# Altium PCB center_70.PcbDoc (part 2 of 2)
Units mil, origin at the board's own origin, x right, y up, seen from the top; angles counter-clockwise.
Board outline 2598.41 x 2598.41 mil, 6 copper layers (Top Layer 1, GND, POWER, SIG, GND (Mid4), Bottom Layer 1), stack 67.411 mil thick; 185 components, 89 nets, 515 pads, 179 vias.
Unrouted connection lines stored in the file: 158.
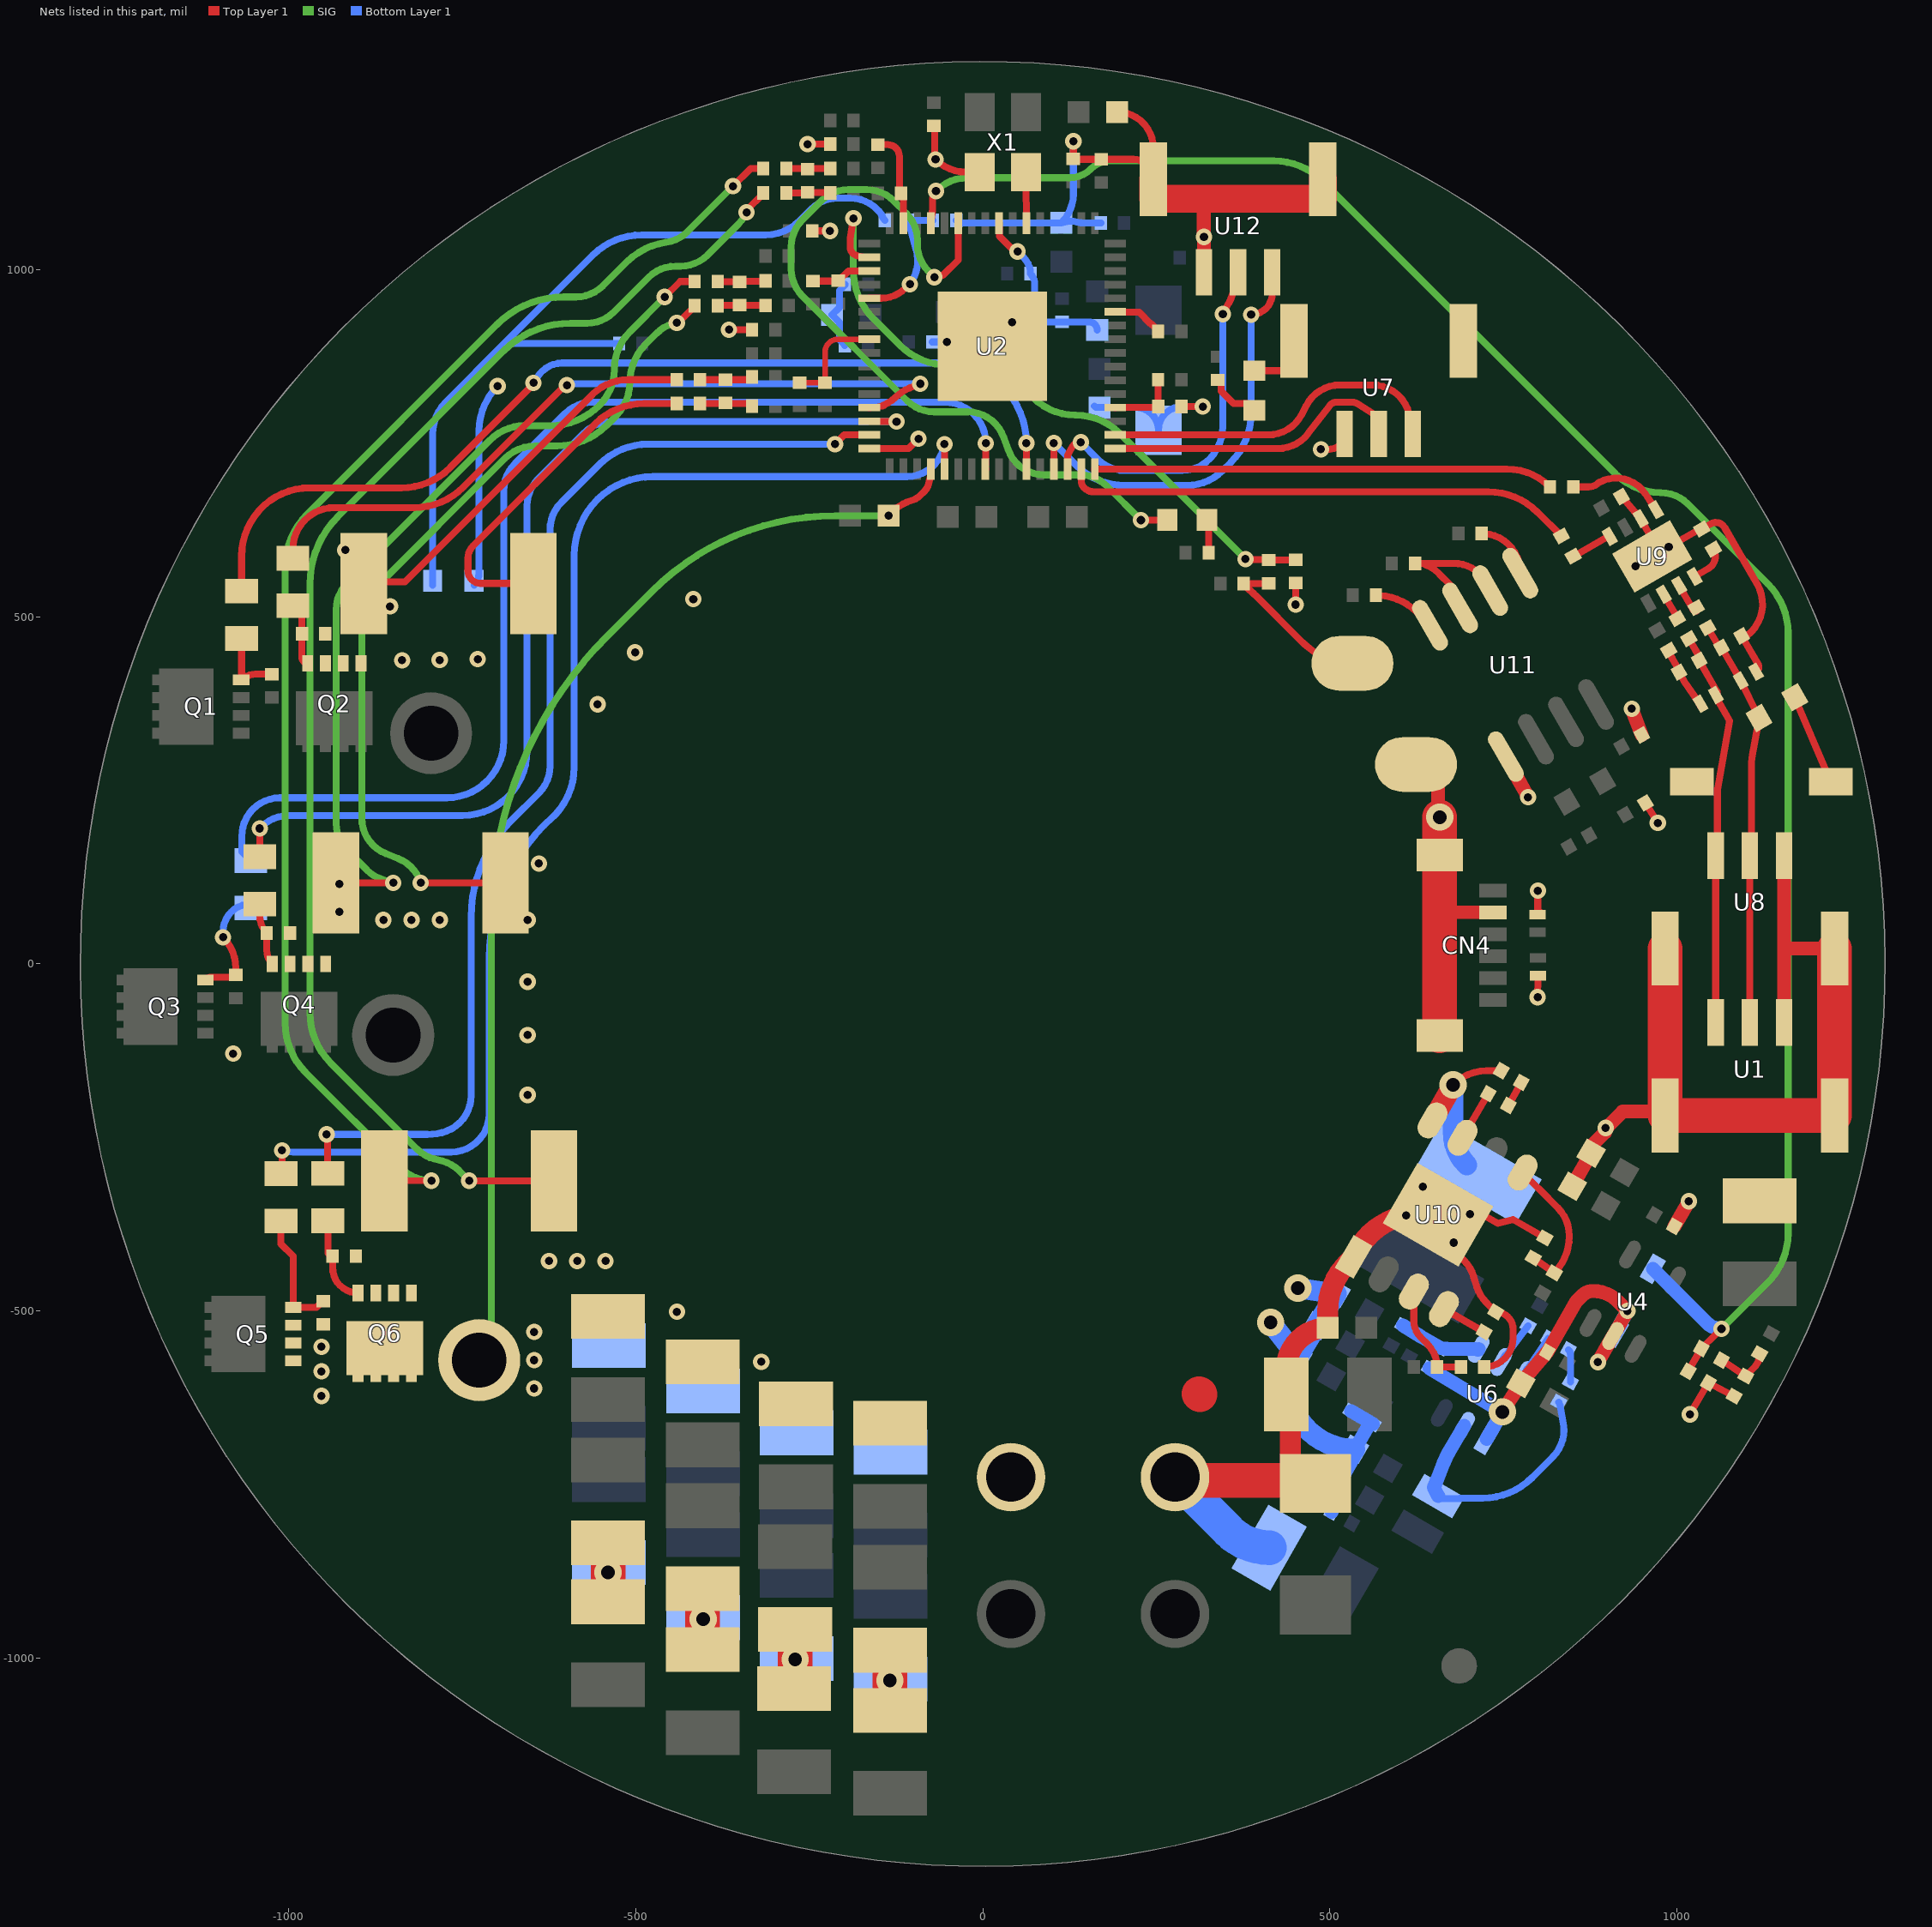
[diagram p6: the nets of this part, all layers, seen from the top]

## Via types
v1: diameter 23.62, hole 11.81, Top Layer 1 to Bottom Layer 1, 146 vias
v2: diameter 39.37, hole 19.68, Top Layer 1 to Bottom Layer 1, 21 vias
v3: diameter 86.61, hole 86.61, Top Layer 1 to Bottom Layer 1, 6 vias
v4: diameter 19.68, hole 11.81, Top Layer 1 to Bottom Layer 1, 4 vias
v5: diameter 19.68, hole 11.81, Top Layer 1 to Bottom Layer 1, tented top, 2 vias

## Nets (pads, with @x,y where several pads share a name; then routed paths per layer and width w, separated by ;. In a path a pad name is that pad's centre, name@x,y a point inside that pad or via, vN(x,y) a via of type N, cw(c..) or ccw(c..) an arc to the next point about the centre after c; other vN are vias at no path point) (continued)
C: C36.1 C.1 Q5.S Q6.D R11.2 U2.36 | length 1650.3
  Top Layer 1 w10: v1(-135.38,645.28) -124.63,656.02 -120.42,658.91 cw(c-89.35,613.52) -108.64,665.03 -97.72,669.12 ccw(c-103.69,685.04) -91.69,673 -82.96,681.72 ccw(c-95,693.72) -78.55,689.46 -77.36,694.03 -75.31,702.04 U2.36@-74.8,712.59
  SIG w10: C.1@-725,-570.47 -723.35,-568.82 ccw(c-762.28,-529.97) -707.28,-529.97 -707.28,68.96 -707.07,84.62 cw(c-136.94,69.06) -540.42,472.17 -476.62,535.97 cw(c-212.74,272.09) -212.74,645.28 v1(-135.38,645.28)
  other v1: -645.87,-611.22 -952.17,-586.61 -645.87,-570.47 -645.87,-529.92
CAN_RX: R30.1 U2.47 | length 739.1
  Top Layer 1 w10: U2.47@141.73,712.59 141.73,695.89 ccw(c156.52,695.89) 146.06,685.43 ccw(c159.85,699.22) 159.85,679.72 728.02,679.72 cw(c728.02,579.72) 798.73,650.44 R30.1@833.19,615.97
CAN_TX: R27.1 U2.48 | length 662.2
  Top Layer 1 w10: U2.48@161.42,712.59 754.5,712.59 cw(c754.5,624.58) R27.1@816.73,686.81
CANH: C30.1 Q7.2 R28.2 R56.1 U1.2 U8.2 | length 571.5
  Top Layer 1 w10: R28.2@1044.05,484.01 1059.8,456.73 ccw(c1062.35,458.21) C30.1@1063.83,455.65 Q7.2@1091.39,407.92 1094.38,401.78 1112.99,363.69 R56.1@1117.71,354.01 1115.28,340.67 1107.97,300.63 ccw(c1162.08,290.76) 1107.08,290.76 1107.08,175.07 U8.2@1107.08,146.6 ; U1.2@1104.52,-84.38 U8.2@1104.52,127.51
CANL: C31.2 Q8.2 R29.2 U1.1 U8.1 U13.1 | length 548.1
  Top Layer 1 w10: R29.2@1016.77,468.26 1032.52,440.98 cw(c1029.96,439.51) C31.2@1031.44,436.95 1057.03,392.62 cw(c1053.62,390.66) Q8.2@1055.59,387.25 ; U1.1@1055.31,-84.38 U8.1@1055.31,155.97 ; Q8.2@1056.57,382.72 1075.39,350.13 1057.87,251.64 U8.1@1057.87,175.07
GND: C3.1 C4.1 C5.1 C6.1 C7.1 C8.1 C9.1 C10.1 C11.1 C12.1 C13.1 C14.1 C15.1 C16.1 C17.1 C19.1 C20.1 C25.1 C28.1 C29.1 C30.2 C31.1 C34.1 C35.1 C38.1 C39.1 C40.1 C42.1 C43.1 C44.1 C45.1 C46.1 C47.1 C48.1 C49.1 C50.1 C51.1 C52.1 C53.1 C54.1 C55.1 C56.1 C57.1 C58.1 C59.1 C60.1 C61.1 C62.1 C63.1 C67.1 C68.1 C70.1 C71.1 C72.1 C73.1 C74.1 C78.1 C79.1 C85.1 C86.1 C87.1 CN1.1 CN2.1 CN4.2 CN4.7 CN4.8 D1.2 NTC2.1 Q7.1 Q8.1 Q9.A Q10.1 Q11.K Q13.A Q14.1 R2.1 R3.1 R5.1 R23.1 R24.1 R25.1 R26.2 R34.1 R36.1 R38.2 R43.1 R50.1 R55.1 R58.1 R59.1 R60.1 R66.2 R79.1 U1.3 U1.4 U1.5 U2.32 U2.65 U4.2 U6.1 U7.3 U7.4 U7.5 U8.3 U8.4 U8.5 U9.2 U9.9 U10.1 U10.9 U11.5 U12.3 U12.4 U12.5 X1.2 | length 11395.8
  Top Layer 1 w10: v1(-809.25,116.73) R55.1@-687.2,116.73 ; v1(-739.38,-312.17) R5.1@-617.33,-312.17 ; R3.1@-647.05,547.83 -723.03,547.83 cw(c-723.03,565.94) -741.14,565.94 -741.14,584.45 cw(c-716.8,584.45) -734.01,601.66 -558.29,777.39 cw(c-487.58,706.68) -487.58,806.68 R34.1@-440.55,806.68 ; v1(-440.55,923.02) -438.67,923.02 -414.96,946.74 R59.1@-414.96,947.72 ; v1(-365.44,913.18) R58.1@-332.09,913.18 ; v1(-339.96,1082.08) -339.96,1085.04 -316.15,1108.85 R36.1@-316.15,1109.84 ; v1(-252.17,1180.21) R60.1@-219.5,1180.21 ; R43.1@-245.28,1055.37 v1@-219.89,1055.36 ; U2.32@-163.19,741.92 -106.7,741.92 v1(-92.52,756.09) ; C48.1@-70.28,1206.69 -69.09,1205.51 -69.09,1159.45 v1(-67.91,1158.27) ccw(c-23.72,1202.47) -23.72,1139.96 X1.2@-4.53,1139.96 ; v1(130.51,1184.45) C50.1@130.51,1159.25 ccw(c131.3,1159.25) 131.3,1158.47 C19.1@170.67,1158.47 216.86,1158.47 cw(c216.86,1129.73) U12.4@245.59,1129.73 245.59,1174.62 ccw(c193.64,1174.62) C44.1@193.64,1226.57 ; R38.2@286.22,802.36 v1(316.73,802.36) ; Q11.K@391.14,854.14 448.03,854.14 U7.4@448.03,897.05 ; C86.1@449.61,548.43 C86.1@450.59,548.43 v1(450.59,517.32) ; v1(487.01,740.94) 498.62,740.94 ccw(c498.62,763.19) U7.3@520.86,763.19 ; U10.9@655.75,-361.12 664.51,-369.88 cw(c625.62,-408.77) 680.09,-401.18 680.1,-401.26 687.48,-422.15 687.69,-422.27 cw(c680.19,-435.27) 690.78,-424.64 692.88,-426.74 cw(c653.94,-465.59) 706.37,-448.96 711.52,-465.19 ccw(c763.94,-448.56) 725.05,-487.45 727.38,-489.78 ccw(c766.37,-450.99) 727.57,-489.97 734.07,-496.47 735.27,-497.17 R23.1@738.63,-501.03 cw(c738.63,-526.11) 763.71,-526.11 763.71,-538.54 cw(c721.94,-538.54) R2.1@721.94,-580.31 ; v4(701.65,-360.35) 713.26,-357.24 741.7,-373.66 763.71,-367.76 R24.1@809.43,-394.16 ; v1(799.02,-47.88) 799.36,-20.72 799.36,-18.82 Q10.1@799.41,-16.93 ; Q14.1@799.02,71.06 804.05,72.95 Q14.1@802.48,74.53 ; v1(799.36,105.51) 799.19,105.34 799.19,72.95 Q14.1@802.48,72.95 ; C20.1@919.65,673.03 922.87,669.3 942.28,646.8 U9.2@947.14,641.17 967.57,605.79 ccw(c980.35,613.17) v5(987.73,600.39) 1033.33,626.72 cw(c1034.07,625.44) R26.2@1035.34,626.18 1048.13,633.56 cw(c1055.51,620.77) 1068.3,628.16 1115.05,547.18 cw(c1064.76,518.14) C30.2@1093.79,467.85 ; R66.2@954.06,231.79 956.62,227.68 v1(972.05,202.95) ; C49.1@987.79,451.53 988.44,447.45 992.36,440.66 cw(c944.77,413.09) 992.54,440.35 992.83,439.85 cw(c945.24,412.27) 992.92,439.68 1001.31,425.15 C31.1@1002.46,420.22 1004.88,416.02 1010.79,405.78 ccw(c1058.33,433.44) 1013.36,401.78 1026.71,382.81 cw(c981.74,351.15) 1028.18,380.61 1028.76,379.62 Q8.1@1034.41,369.92 ; v1(1018.24,-648.55) 1042.36,-607.43 C29.1@1044.81,-603.25 1048.35,-604.83 1051.88,-606.87 1077.57,-620.03 R50.1@1081.89,-622.24 ; C30.2@1092.81,472.38 1116.43,431.47 cw(c1109.61,427.53) Q7.1@1113.55,420.71
  Top Layer 1 w20: 318.31,1101.69 318.31,1046.65 v1(318.5,1046.65) 318.5,995.87 U12.3@318.43,995.87 ; NTC2.1@655.51,271.71 655.51,213.94 v2(658.07,211.38) ; 658.07,74.53 CN4.2@734.84,74.01 ; v2(748.03,-644.88) 769.28,-612.19 ccw(c677.06,-552.23) 771.58,-608.5 C13.1@774.79,-603.72 778.9,-599.45 778.94,-599.38 cw(c868.45,-663.33) 784.37,-592.4 C14.1@812.87,-558.71 854.45,-486.34 863.72,-477.06 cw(c878.55,-491.88) 878.55,-470.92 cw(c878.55,-521.82) 914.54,-485.83 v1(928.35,-499.63) 913.48,-525.37 U4.2@907.58,-535.6 901.67,-545.83 v1(885.83,-573.28) ; U11.5@753.21,298.49 765.16,277.78 764.67,277.5 v1(785.16,239.99) ; C15.1@848.78,-320.32 851.61,-315.32 873.11,-277.41 C16.1@875.94,-272.41 875.94,-262.52 896.26,-242.21 896.26,-236.41 v1@895.97,-236.12 ; v1(896.95,-236.12) 897.93,-236.12 921.48,-212.57 U1.5@970.46,-212.57 ; v1(934.45,367.54) C85.1@948.94,329.63 ; C17.1@995.94,-378.01 v1(1016.55,-341.79) ; U1.3@1153.74,-84.38 1153.74,22.11 ; U8.3@1153.74,155.97 1153.74,22.11 ; U8.4@1226.57,22.11 1153.74,22.11
  Top Layer 1 w30: Q13.A@479.22,-747.76 470.37,-747.76 443.04,-720.44 443.04,-625.75 C72.1@437.16,-619.87 437.16,-583.44 cw(c496.65,-583.44) C3.1@496.65,-523.96 496.65,-500.7 cw(c596.65,-500.7) 525.93,-429.99 U10.1@534.1,-421.82 ; U10.1@540.46,-410.81 cw(c627.06,-460.81) 601.18,-364.22 v4(609.84,-361.89)
  Top Layer 1 w40: U12.4@245.59,1129.73 245.6,1102.01 245.91,1101.69 318.31,1101.69 489.37,1101.69 489.37,1101.38 489.69,1101.69 U12.5@489.69,1129.73
  Top Layer 1 w50: C67.1@-539.38,-918.41 C53.1@-539.38,-833.56 ; C68.1@-403.35,-987.31 C71.1@-403.35,-899.5 ; C73.1@-271.46,-1043.41 ccw(c-271.46,-1042.03) -270.08,-1042.03 C54.1@-270.08,-958.36 ; C34.1@-133.46,-1074.71 C55.1@-133.46,-988.09 ; CN1.1@276.87,-738.91 281.29,-743.34 474.79,-743.34 Q13.A@479.22,-747.76 ; 311.67,-618.83 ccw(c312.7,-618.83) 312.7,-619.87 ; CN4.7@658.07,-103.15 658.07,74.53 CN4.8@658.07,156.69 v2(658.07,211.38) ; U8.5@982.48,22.11 982.48,-212.57 U1.5@982.48,-218.24 U1.4@1226.57,-218.24 U8.4@1226.57,22.11
  SIG w10: v1(-809.25,116.73) ccw(c-861.81,100.54) -841.49,151.65 -859.33,158.76 cw(c-839.09,209.91) -894.09,209.91 -894.09,498.83 cw(c-839.09,498.83) -878.03,537.68 -687.98,727.73 cw(c-644.56,684.31) -644.56,745.71 -612.84,745.71 ccw(c-612.84,845.71) -542.16,774.97 -527.95,789.17 ccw(c-576.2,837.42) -507.97,837.42 cw(c-430.3,837.42) -485.22,892.34 -469.75,907.81 cw(c-430.91,868.87) -440.64,923 v1(-440.55,923.02) ; v1(-739.38,-312.17) -739.47,-312.07 -753.67,-297.87 ccw(c-792.56,-336.77) -779.29,-283.39 -789.03,-280.97 cw(c-775.98,-227.54) -814.87,-266.43 -939.44,-141.86 cw(c-868.7,-71.18) -968.7,-71.18 -968.7,307.05 -968.7,547.1 cw(c-831.96,547.1) -928.76,643.69 -689.99,882.45 cw(c-593.4,785.66) -593.4,922.4 -570.07,922.4 ccw(c-570.07,977.4) -531.22,938.46 -481.22,988.46 cw(c-442.38,949.53) -442.38,1004.53 -435.18,1004.53 ccw(c-435.18,1059.53) -396.33,1020.59 -351.22,1065.7 ccw(c-390.16,1104.55) v1(-339.96,1082.08)
  Bottom Layer 1 w10: R79.1@-732.43,545.28 ccw(c-749.4,562.25) -725.39,562.25 -725.39,767.26 cw(c-633.99,767.26) v1(-698.62,831.89) ; C39.1@-198.62,890.16 -198.62,891.14 -206.23,898.75 -206.23,923.7 C38.1@-216.98,934.45 -206.23,945.2 -206.23,969.55 -198.23,977.56 C28.1@-198.23,978.54 ; C40.1@-72.83,895.47 v1(-51.53,895.47) -51.33,895.28 -31.3,895.28 C51.1@-31.1,895.08 ; C87.1@-38.19,1070.47 ccw(c-29.32,1079.34) -29.32,1066.8 C6.1@113.19,1066.8 ; v1@44.93,926.62 v1(42.32,924.02) 113.89,924.02 C7.1@114.19,924.31 152.95,924.31 cw(c152.95,912.45) C47.1@164.82,912.45 ; v1(130.51,1184.45) 130.51,1108.62 cw(c71.37,1108.62) C6.1@113.19,1066.8 ; C25.1@160.77,803.35 162.99,801.13 220.23,801.13 cw(c220.23,768.4) D1.2@252.95,768.4 cw(c286.91,768.4) 286.91,802.36 v1(316.73,802.36) ; C52.1@170.13,1066.8 146.78,1066.8 cw(c146.88,1121.8) 130.51,1069.29 123.94,1069.29 C6.1@113.19,1066.8 ; C45.1@316.93,1016.93 316.93,1045.08 cw(c318.5,1045.08) v1(318.5,1046.65)
  Bottom Layer 1 w20: C12.1@502.47,-788.88 C11.1@507.3,-756.12 ; C43.1@530.41,-644.02 C9.1@561.91,-662.33 ; C10.1@535.89,-698.68 538.58,-693.97 540.23,-691.1 C9.1@556.68,-662.37 ; R25.1@643.11,-582.09 v2(748.03,-644.88) U6.1@725.7,-683.82 ; Q9.A@911.61,-530.87 v1(928.35,-499.63)
  Bottom Layer 1 w30: v2(414.55,-516) 450.27,-562.06 ccw(c580.5,-460.75) 453.16,-565.67 453.3,-565.75 C35.1@453.73,-566.52 ; v2(453.73,-466.67) 507.62,-474.51 cw(c483.89,-637.79) 507.99,-474.56 508.1,-474.62 508.98,-474.7 508.71,-475.15 C5.1@508.67,-475.22 ; C5.1@508.66,-475.25 cw(c366.14,-392.1) 507.8,-476.71 507.22,-477.67 481.99,-518.67 ccw(c622.58,-605.03) 481.22,-519.93 C8.1@480.82,-520.57 480.44,-521.22 480.28,-521.49 455.09,-564.21 ccw(c597.3,-647.88) 454.49,-565.23 454.12,-565.87 C35.1@453.73,-566.52 ; C11.1@509.08,-744 C10.1@535.25,-698.68 ; C10.1@529.79,-698.68 C10.1@535.25,-698.68 ; C10.1@535.89,-698.68 cw(c535.89,-601.87) C10.1@535.25,-698.68 ; C35.1@453.73,-566.52 ccw(c489.08,-601.87) 439.08,-601.87 ccw(c535.89,-601.87) C10.1@535.25,-698.68
  Bottom Layer 1 w50: CN1.1@276.87,-738.91 354.19,-816.23 ccw(c412.51,-757.91) C42.1@412.51,-840.39
  other v1: -952.17,-622.05 -318.85,-572.78 -952.17,-551.18 -440.35,-500.79 -624.42,-427.79 -583.87,-427.79 -543.12,-427.79 -655.38,-188.57 -1079.33,-129.13 -655.38,-102.36 -655.38,-25.58 -655.38,63.19 -639.1,144.58 -554.61,373.84 -500.61,448.46 -416.73,525.2 -219.87,1055.34
  other v2: -133.66,-1031.5 -270.08,-1001.57 -402.76,-943.5 -539.57,-876.18
  other v4: 678.03,-401.26 633.46,-320.98
  other v5: 940,572.83
IA: C24.1 R39.2 U2.24 | length 154.9
  Top Layer 1 w8: C24.1@-263.58,836.99 R39.2@-227.17,836.99 ; R39.2@-227.17,836.79 R39.2@-227.17,836.99 ; U2.24@-163.19,899.4 -208.28,899.4 ccw(c-208.28,880.51) -227.17,880.51 R39.2@-227.17,836.99
IA_N: C21.1 R34.2 R42.1 | length 77.4
  Top Layer 1 w10: R34.2@-407.08,806.68 -371.26,806.68 ccw(c-371.26,807.66) C21.1@-370.28,807.66 -365.44,807.06 -335.94,807.06 R42.1@-332.09,802.94
IA_P: C21.2 R31.2 R45.1 | length 76.3
  Top Layer 1 w10: R31.2@-407.08,841.13 C21.2@-370.28,841.13 -341.59,841.13 ccw(c-341.59,854.56) R45.1@-332.09,845.06 ; R45.1@-333.27,845.26 R45.1@-333.07,845.06
IB: C22.1 R4.2 U2.19 | length 87.7
  Top Layer 1 w10: C22.1@-244.29,983.06 -208.28,983.06 R4.2@-208.28,983.93 -207.3,983.93 -193.4,997.83 U2.19@-163.19,997.83
IB_N: C26.1 R32.1 R59.2 | length 69.1
  Top Layer 1 w10: R59.2@-381.49,947.72 -381.14,948.07 -350.15,948.07 C26.1@-349.8,948.43 -349.55,948.17 -313.16,948.17 R32.1@-312.91,947.92
IB_P: C26.2 R35.1 R46.2 | length 69.4
  Top Layer 1 w10: R46.2@-381.49,982.48 -381.2,982.19 -350.1,982.19 C26.2@-349.8,981.89 -349.08,982.61 -313.62,982.61 R35.1@-312.91,983.33
IC: C27.1 R41.2 U2.15 | length 140.1
  Top Layer 1 w10: C27.1@-150.99,1179.53 -136.74,1179.53 cw(c-136.74,1162.79) -120.01,1162.79 -120.01,1111.74 cw(c-120.01,1105.9) -114.17,1105.9 U2.15@-114.17,1066.52
IC_N: C23.1 R36.2 R44.1 | length 64.3
  Top Layer 1 w10: R36.2@-282.68,1109.84 -253.15,1109.84 ccw(c-253.15,1110.82) C23.1@-252.17,1110.82 -220.48,1110.82 cw(c-220.48,1109.84) R44.1@-219.5,1109.84
IC_P: C23.2 R33.2 R47.1 | length 63.2
  Top Layer 1 w10: R33.2@-282.68,1145.27 -251.19,1145.27 R47.1@-219.5,1145.27
LED_RUN: Q12.K U2.11 | length 1157.4
  Top Layer 1 w10: v1(-69.61,988.66) -67,991.26 -57.55,991.26 -35.4,1013.42 U2.11@-35.43,1066.52 ; v1(227.76,638.97) Q12.K@265.74,638.97
  SIG w10: v1(-69.61,988.66) -78.03,997.08 cw(c-39.09,1035.93) -94.09,1035.93 -94.09,1041.79 ccw(c-149.09,1041.79) -110.16,1080.63 -128.22,1098.7 ccw(c-167.07,1059.76) -167.07,1114.76 -193.36,1114.76 ccw(c-193.36,1059.76) -232.21,1098.7 -259.72,1071.18 ccw(c-220.79,1032.34) -275.79,1032.34 -275.79,1000.54 ccw(c-220.79,1000.54) -259.72,961.69 -108.98,810.95 ccw(c-70.13,849.88) -70.13,794.88 -21.73,794.88 cw(c-21.73,739.88) 30,758.56 36.54,740.45 ccw(c88.27,759.13) 88.27,704.13 139.81,704.13 cw(c139.81,649.13) 178.66,688.07 227.7,639.03 cw(c188.91,600.04) v1(227.76,638.97)
MOS_T: C87.2 R78.2 U2.21 | length 196.5
  Top Layer 1 w10: U2.21@-163.19,958.46 -146.41,958.46 ccw(c-146.41,1008.22) -111.22,973.03 -106.27,977.99 cw(c-104.92,976.64) v1(-104.92,978.54)
  Bottom Layer 1 w10: v1(-104.92,978.54) ccw(c-149.11,1011.29) -95.82,997.69 -95.35,999.5 ccw(c-148.62,1013.19) -95.61,1027.84 -105.83,1064.73 cw(c-91.35,1068.64) -106.09,1065.83 R78.2@-107.48,1070.67 -103.62,1070.47 C87.2@-71.65,1070.47
MOTOR_T: C86.2 R77.2 U2.18 | length 964.8
  Top Layer 1 w10: v1(-186.22,1073.43) -190.6,1044.51 ccw(c-178.74,1042.71) -190.74,1042.71 -190.74,1031.68 ccw(c-178.74,1031.68) -181.71,1020.06 -173.74,1018.02 U2.18@-163.19,1017.51 ; v1(378.35,582.87) 379.04,582.19 411.32,582.19 R77.2@412.01,581.5 412.2,581.69 450.39,581.69 C86.2@450.59,581.89
  SIG w10: v1(-186.22,1073.43) -186.22,999.03 ccw(c-86.22,999.03) -156.99,928.37 -119.86,891.24 ccw(c-49.2,962.01) -49.2,862.01 -15.63,862.01 cw(c-15.63,762.01) 55.17,832.62 72.36,815.44 ccw(c133.27,876.18) 133.27,790.16 133.66,790.16 cw(c133.66,699.86) 197.61,763.61 v1(378.35,582.87)
NetC1_1: C1.1 L1.1 U10.8 | length 255.2
  Top Layer 1 w10: v2(677.15,-173.91) cw(c725.56,-222.32) 725.56,-153.86 C1.1@746.56,-153.86
  Top Layer 1 w30: U10.8@647.49,-225.43 v2(677.15,-173.91)
  Bottom Layer 1 w30: v2(677.15,-173.91) 677.15,-241.39 ccw(c745.21,-241.39) L1.1@697.09,-289.52
NetC1_2: C1.2 R18.2 | length 37.9
  Top Layer 1 w10: R18.2@756.92,-203.6 759.3,-199.38 759.75,-198.59 773.16,-174.81 C1.2@775.54,-170.59
NetC2_1: C2.1 L2.1 U6.2 | length 378.5
  Bottom Layer 1 w10: L2.1@659.8,-769.74 686.88,-769.5 719.77,-769.21 ccw(c719,-666.62) 791.47,-739.24 820.74,-709.96 ccw(c781.81,-671.12) 836.81,-671.12 836.81,-670.87 ccw(c781.81,-670.87) 835.99,-661.41 831.69,-636.79 C2.1@829.43,-631.03
  Bottom Layer 1 w20: L2.1@655.87,-766.28 649.34,-753.6 649.41,-753.49 ccw(c551.02,-704.3) 653.58,-744.08 662.94,-719.88 cw(c765.65,-759.26) 670.9,-703.38 ccw(c576.04,-647.69) 671.04,-703.14 686.55,-676.66 cw(c781.64,-731.95) 688.58,-673.3 U6.2@693.31,-665.12
NetC2_2: C2.2 R19.2 | length 47.2
  Bottom Layer 1 w10: R19.2@843.43,-555.61 cw(c836.83,-562.21) 846.16,-562.21 C2.2@846.16,-602.04
NetC18_1: C18.1 R22.1 R25.2 U6.4 | length 119.1
  Bottom Layer 1 w20: C18.1@605.02,-520.35 R22.1@630.81,-536.49 R25.2@659.84,-553.11 ccw(c676.44,-444.36) 676.29,-554.36 706.12,-554.36 cw(c706.03,-574.36) 713.28,-555.72 U6.4@714.06,-554.36
NetNTC1_1: NTC1.1 R75.1 R77.1 | length 236.9
  Top Layer 1 w10: R77.1@412.01,548.03 407.17,547.93 406.04,547.93 ccw(c406.04,492.93) 405.16,547.92 381.79,547.54 cw(c380.91,602.53) 380.91,547.53 379.65,547.53 R75.1@375.79,547.44 379.65,542.6 390.75,532.41 cw(c353.56,491.89) 392.45,530.78 459.02,464.2 ccw(c497.84,503.17) 463.38,460.31 482.22,445.09 ccw(c516.78,487.87) 508.41,433.51 512.6,432.87 NTC1.1@532.28,432.87
NetQ1_G: Q1.G R6.2 R9.1 | length 105.9
  Top Layer 1 w10: R6.2@-1067.08,468.45 -1067.08,408.86 cw(c-1047.11,388.89) -1047.11,417.13 R9.1@-1022.98,417.13
NetQ2_G: Q2.G R12.2 R15.1 | length 95.6
  Top Layer 1 w10: R12.2@-993.45,515.73 cw(c-993.45,502.54) -980.26,502.54 R15.1@-980.26,475.14 -980.26,441.54 ccw(c-971.41,441.54) Q2.G@-971.41,432.68
NetQ2_S: Q2.S R3.2 R15.2 R31.1 | length 568.9
  Top Layer 1 w10: R3.2@-891.14,547.83 -889.15,549.83 -831.87,549.83 -561.89,819.8 cw(c-510.41,768.31) -510.41,841.13 R31.1@-440.55,841.13
  other v1: -836.05,437.2 -781.89,437.6 -727.17,438.78 -853.35,514.82 -917.91,595.87
NetQ3_G: Q3.G R7.2 R10.1 | length 171.2
  Top Layer 1 w10: Q3.G@-1119.28,-23.03 cw(c-1110.25,-32.06) -1110.25,-19.29 R10.1@-1079.33,-19.29 ; v1(-1093.9,38.39) cw(c-1138.57,-6.29) -1075.39,-6.29 R10.1@-1075.39,-15.94
  Bottom Layer 1 w10: v1(-1093.9,38.39) -1093.9,46.24 cw(c-1053.73,46.24) R7.2@-1053.73,86.42
NetQ4_G: Q4.G R13.2 R16.1 | length 90.9
  Top Layer 1 w10: R13.2@-1040.93,86.02 -1040.93,68.69 ccw(c-1006.7,68.69) R16.1@-1030.91,44.49 -1030.91,19.49 ccw(c-1003.35,19.49) Q4.G@-1022.83,0
NetQ4_S: Q4.S R16.2 R46.1 R55.2 | length 1261
  Top Layer 1 w10: R55.2@-931.3,116.73 v1(-848.82,116.73) ; v1(-457.87,960.24) -435.63,982.48 R46.1@-414.96,982.48
  SIG w10: v1(-848.82,116.73) -864.63,121.82 cw(c-847.94,174.23) -886.75,135.26 -914.84,163.35 cw(c-875.91,202.2) -930.91,202.2 -930.91,509.9 cw(c-875.91,509.9) -914.84,548.74 -709.24,754.34 cw(c-659.37,704.46) -659.37,775 -622.52,775 ccw(c-622.52,875) -551.81,804.29 ccw(c-603.24,855.72) -530.51,855.72 cw(c-453.54,855.72) -507.97,910.14 v1(-457.87,960.24)
  other v1: -862.99,63.19 -822.44,63.19 -781.69,63.19 -926.38,74.8 -926.38,115.35
NetQ5_G: Q5.G R8.2 R11.1 | length 178.4
  Top Layer 1 w10: R8.2@-1010.43,-370.12 -1010.43,-402.98 -992.71,-420.71 Q5.G@-992.71,-494.49 -959.49,-494.49 -950.63,-485.63 R11.1@-949.65,-485.63
NetQ6_G: Q6.G R14.2 R17.1 | length 128.7
  Top Layer 1 w10: R14.2@-942.91,-369.92 -942.91,-413.82 ccw(c-936.02,-413.82) R17.1@-936.02,-420.71 -936.02,-437.21 ccw(c-899.41,-437.21) Q6.G@-899.41,-473.82
NetQ6_S: Q6.S R5.2 R17.2 R33.1 | length 2003.5
  Top Layer 1 w10: R5.2@-884.85,-260.39 R5.2@-860.96,-260.61 ; R5.2@-862.03,-311.55 -861.42,-311.55 v1(-793.84,-312.17) ; v1(-359.65,1119.68) -334.06,1145.27 R33.1@-316.15,1145.27
  SIG w10: v1(-793.84,-312.17) cw(c-793.84,-251.53) -836.71,-294.41 -975.07,-156.05 cw(c-904.33,-85.37) -1004.33,-85.37 -1004.33,570.55 cw(c-895.05,570.55) -972.38,647.76 -699.93,920.22 cw(c-603.24,823.43) -603.24,960.24 -585.7,960.24 ccw(c-585.7,1015.24) -546.86,976.3 -512.68,1010.47 cw(c-441.97,939.76) -456.03,1038.77 ccw(c-463.91,1093.2) -425.1,1054.23 v1(-359.65,1119.68)
NetQ11_A: Q11.A R51.1 | length 78.1
  Top Layer 1 w10: R51.1@338.19,840.75 339.17,840.75 343.03,836.89 343.03,824.91 361.13,806.81 381.37,806.81 Q11.A@391.14,797.05
NetQ12_A: Q12.A R52.1 | length 46.9
  Top Layer 1 w10: Q12.A@322.83,642.12 cw(c316.65,635.94) 325.39,635.94 R52.1@325.39,595.87
NetR1_2: R1.2 R2.2 U10.3 | length 153.2
  Top Layer 1 w10: U10.3@620.71,-471.82 620.71,-513.68 ccw(c654.66,-513.68) 630.65,-537.68 640.66,-547.7 cw(c608.05,-580.31) R1.2@654.17,-580.31 R2.2@688.47,-580.31
NetR18_1: R18.1 U10.7 | length 73.8
  Top Layer 1 w10: U10.7@690.79,-250.43 691.06,-250.35 727.67,-186.94 R18.1@727.94,-186.87
NetR19_1: R19.1 U6.6 | length 64.5
  Bottom Layer 1 w10: U6.6@778.85,-591.77 784.12,-582.63 784.75,-582.99 811.37,-543.45 811.7,-542.88 R19.1@814.45,-538.88
NetR20_1: R20.1 R24.2 U10.5 | length 213.3
  Top Layer 1 w10: U10.5@777.39,-300.43 776.99,-301.12 777.09,-301.17 cw(c745.08,-345.9) 784.05,-307.09 814.77,-337.81 cw(c775.97,-376.79) 814.95,-337.98 827.56,-350.59 cw(c786.71,-391.62) 844.6,-391.62 844.6,-392.45 cw(c770.62,-392.45) 829.21,-437.62 ccw(c872.86,-471.08) 826.1,-442.13 R20.1@822.93,-444.76 819,-441.88 cw(c848.18,-395.25) 816.54,-440.25 798.03,-427.17 ccw(c789.42,-439.46) 796.92,-426.47 796.54,-426.24 R24.2@792.62,-423.35
NetR21_2: R21.2 U6.5 | length 66.1
  Bottom Layer 1 w10: U6.5@746.46,-573.07 751.92,-563.6 753.01,-564.23 782.79,-524.06 R21.2@785.11,-520.94
NetR23_2: R23.2 U10.4 | length 66.9
  Top Layer 1 w10: U10.4@664.01,-496.82 664.11,-496.65 R23.2@721.9,-530.01
NetR26_1: R26.1 U9.8 | length 55.1
  Top Layer 1 w10: U9.8@1024.91,557.64 1044.51,568.96 ccw(c1034.18,586.86) R26.1@1052.08,597.2
NetR27_2: R27.2 U9.1 | length 141.9
  Top Layer 1 w10: R27.2@850.2,686.81 871.95,686.81 ccw(c871.95,708.18) 887.06,693.07 cw(c911.83,648.83) 954.05,676.9 964.96,660.48 cw(c952.43,652.23) 965.23,660.05 U9.1@969.3,653.96
NetR28_1: R28.1 U9.7 | length 46.5
  Top Layer 1 w10: U9.7@1002.75,544.85 1022.93,509.9 ccw(c1026.34,511.86) R28.1@1028.3,508.46
NetR29_1: R29.1 U9.6 | length 45.4
  Top Layer 1 w10: U9.6@980.58,532.05 R29.1@1001.74,495.4 ; R29.1@1000.04,497.24 ccw(c999.05,498.94) R29.1@1000.76,499.93
NetR30_2: R30.2 U9.4 | length 60.5
  Top Layer 1 w10: R30.2@850.32,586.3 901.61,615.91 U9.4@902.82,615.58
NetR37_1: R37.1 R38.1 U2.52 | length 101.4
  Top Layer 1 w10: U2.52@190.75,800.98 191.26,801.49 251.88,801.49 R38.1@252.76,802.36 252.66,802.46 252.66,841.04 R37.1@252.56,841.14
NetR48_1: R48.1 R49.1 R50.2 | length 81
  Top Layer 1 w10: R49.1@1063.7,-570.37 1066.94,-572.49 1094.57,-590.6 R50.2@1098.62,-593.26 1110.36,-581.53 ccw(c1089.97,-561.14) R48.1@1118.8,-561.14
NetR53_1: R53.1 U2.59 | length 74
  Top Layer 1 w10: U2.59@190.75,938.77 191.26,938.25 225.13,938.25 241.57,921.81 242.56,921.81 252.56,911.81 R53.1@252.56,910.83
NetR56_2: R56.2 U13.2 | length 132.3
  Top Layer 1 w10: R56.2@1169.29,383.79 1173.55,373.84 1213.66,280.16 1213.66,277.09 U13.2@1221.26,262.4
NetR71_2: R71.2 U11.1 | length 88.9
  Top Layer 1 w10: R71.2@718.31,619.69 722.17,619.55 cw(c718.31,564.03) 773.96,564.03 U11.1@773.96,562.54
NetR73_2: R73.2 U11.2 U11.3 | length 215.6
  Top Layer 1 w10: R73.2@622.44,576.77 R73.2@631.27,576.77 ; U11.3@687.31,512.62 U11.3@687.36,512.54 ; U11.3@687.32,512.63 ccw(c632.47,508.65) 671.36,547.54 658.19,560.7 ccw(c619.25,521.86) 658.14,560.76 656.51,562.38 ccw(c617.62,523.49) 631.38,576.74 R73.2@631.27,576.77 ; U11.2@730.66,537.54 717.4,560.49 717.21,560.38 cw(c726.86,571.87) 716.58,560.94 715.65,561.82 ccw(c677.95,521.77) 677.95,576.77 R73.2@631.27,576.77
NetR74_2: R74.2 U11.4 | length 92.2
  Top Layer 1 w10: R74.2@566.14,530.71 570,530.58 570.79,530.58 cw(c567.94,475.65) 571.18,530.56 cw(c566.14,446.83) 625.51,506.09 625.56,506.04 U11.4@644.06,487.54
NetR76_1: R76.1 R78.1 R79.2 | length 1190.6
  Bottom Layer 1 w10: R79.2@-791.98,545.28 -791.98,762.55 cw(c-725.93,762.55) -772.66,809.23 -688.78,893.11 ; R76.1@-523.62,893.11 -688.78,893.11 ; R78.1@-140.94,1070.67 -144.38,1075.51 ccw(c-158.85,1071.55) -144.53,1076.03 -145.24,1078.29 ccw(c-190.85,1047.56) -190.85,1102.56 -208.32,1102.56 ccw(c-208.32,1047.56) -247.17,1086.49 -263.78,1069.88 cw(c-312.73,1118.83) -312.73,1049.61 -490.86,1049.61 ccw(c-490.86,949.61) -561.57,1020.32 -688.78,893.11
OSC: U2.6 X1.3 | length 73.4
  Top Layer 1 w10: X1.3@62.4,1139.96 62.58,1117.4 62.91,1077.08 U2.6@62.99,1066.52
PWM_AH: R6.1 U2.43 | length 1410.8
  Top Layer 1 w10: R6.1@-1067.08,536.64 -1067.08,587.25 cw(c-968.9,587.25) -968.9,685.43 -837.29,685.43 ccw(c-837.29,785.43) -766.58,714.72 -646.85,834.45 v1(-646.85,836.61) ; v1(62.8,749.8) 62.8,723.14 U2.43@62.99,712.59
  Bottom Layer 1 w10: v1(-646.85,836.61) cw(c-597.97,811.4) -638.76,848.3 cw(c-605.38,823.7) -605.46,865.16 -52.56,865.16 cw(c-52.56,749.8) v1(62.8,749.8)
PWM_AL: R12.1 U2.29 | length 1102.8
  Top Layer 1 w10: R12.1@-993.45,583.92 -993.45,596.7 cw(c-933.07,596.7) -933.07,657.09 -818.58,657.09 ccw(c-818.58,757.09) -747.87,686.38 -600.98,833.27 v1(-598.62,833.27) ; U2.29@-163.19,800.98 -152.64,801.49 -144.68,803.52 ccw(c-147.64,815.14) -141.61,804.77 -135.31,808.43 ccw(c-162.96,855.98) -126.09,815.16 -121.71,819.12 cw(c-85.01,778.15) -104.94,829.42 v1(-89.96,835.24)
  Bottom Layer 1 w10: v1(-598.62,833.27) -596.65,835.24 v1(-89.96,835.24)
PWM_BH: R7.1 U2.40 | length 1682.5
  Top Layer 1 w10: U2.40@3.94,712.59 4.45,723.14 v1(4.53,749.61)
  Bottom Layer 1 w10: R7.1@-1053.73,148.7 -1066.7,161.41 -1066.7,184.17 cw(c-1011.7,184.17) -1063.55,202.5 -1063.38,202.99 cw(c-1040.93,195.06) -1063.11,203.73 -1062.92,204.21 cw(c-1011.7,184.17) -1011.8,239.17 -771.85,239.17 ccw(c-771.85,321.46) -689.57,321.46 -689.57,681.4 cw(c-634.57,681.4) -673.5,720.25 -601.16,792.59 cw(c-562.31,753.66) -562.31,808.66 -54.53,808.66 cw(c-54.53,749.61) v1(4.53,749.61)
PWM_BL: R13.1 U2.30 | length 1470.9
  Top Layer 1 w10: R13.1@-1040.93,154.21 v1(-1040.93,195.06) ; U2.30@-163.19,781.29 -162.68,780.77 v1@-120.35,780.77
  Bottom Layer 1 w10: v1(-1040.93,195.06) -1038.47,197.52 cw(c-999.62,158.58) -999.62,213.58 -749.41,213.58 ccw(c-749.41,306.89) -656.1,306.89 -656.1,659.47 cw(c-601.1,659.47) -640.04,698.32 -573.52,764.84 cw(c-534.67,725.91) -534.67,780.91 v1@-124.02,780.91
  other v1: -124.09,780.77
PWM_CH: R8.1 U2.37 | length 1857.9
  Top Layer 1 w10: R8.1@-1008.86,-300 v1(-1008.86,-268.5) ; U2.37@-55.12,712.59 -55.12,723.14 v1(-55.12,748.43)
  Bottom Layer 1 w10: v1(-1008.86,-268.5) -1008.8,-268.52 ccw(c-992.91,-215.87) -993.02,-270.87 -765.7,-270.87 ccw(c-765.7,-215.87) -710.7,-215.87 -710.7,8.37 cw(c-438.5,7.8) -618.86,211.67 ccw(c-655.38,252.79) -615.39,215.03 ccw(c-688.19,283.59) -588.19,283.59 -588.19,588.39 cw(c-475,588.39) -475,701.57 -109.51,701.57 ccw(c-109.51,756.57) v1(-55.12,748.43)
PWM_CL: R14.1 U2.31 | length 1670.5
  Top Layer 1 w10: v1(-944.68,-245.47) -943.57,-246.59 -943.57,-301.08 R14.1@-942.91,-301.73 ; v1(-212.63,748.43) -199.45,761.61 U2.31@-163.19,761.61
  Bottom Layer 1 w10: v1(-944.68,-245.47) -799.92,-245.47 ccw(c-799.81,-156.11) -778.56,-242.91 ccw(c-791.69,-189.5) -736.69,-189.5 -736.69,66.52 -736.05,82.5 cw(c-539.22,66.62) -679.01,206.09 -639.1,246 ccw(c-678.04,284.85) -623.04,284.85 -623.04,625.3 cw(c-568.04,625.3) -606.97,664.14 -551.98,719.14 cw(c-481.27,648.43) -481.27,748.43 v1(-212.63,748.43)
RST: C46.2 R72.1 U2.8 | length 129.8
  Top Layer 1 w10: U2.8@23.62,1066.52 24.13,1066.01 24.13,1047.67 43.41,1028.39 47.59,1028.39 v1(50.2,1025.79)
  Bottom Layer 1 w10: v1(50.2,1025.79) 59.1,1016.89 cw(c35.91,993.7) R72.1@68.7,993.7 cw(c53.97,978.97) 74.8,978.97 C46.2@74.8,958.07
SWCLK: U2.50 U7.1 | length 502.4
  Top Layer 1 w10: U2.50@190.75,761.61 410.63,761.61 ccw(c410.63,816.61) 459.7,791.76 465.82,803.73 cw(c514.76,778.63) 492.37,828.87 cw(c514.83,778.66) 514.83,833.66 560.62,833.66 cw(c560.62,778.66) 613.96,792.08 613.96,791.65 U7.1@619.29,763.19
SWDIO: U2.49 U7.2 | length 434.7
  Top Layer 1 w10: U2.49@190.75,741.92 424.9,741.92 ccw(c424.8,796.92) 468.43,763.43 499.53,803.96 cw(c509.05,796.65) 509.05,808.65 532.67,808.65 cw(c532.67,796.65) 539.04,806.82 563.27,791.65 U7.2@570.08,763.19
USART1_RX: U2.46 U12.2 | length 530.9
  Top Layer 1 w10: U2.46@122.05,712.59 122.05,731.07 cw(c173.83,712.89) 127.61,742.48 cw(c141.91,735.82) v1@141.11,751.57 ; v1(345.67,935.63) cw(c394.55,910.41) 346.46,937.11 353.92,950.54 ccw(c305.83,977.24) 357.42,958.17 360.83,967.4 U12.2@367.64,995.87
  Bottom Layer 1 w10: v1(141.14,750.98) 165.58,726.54 ccw(c204.47,765.43) 204.47,710.43 287.35,710.43 ccw(c287.24,765.43) 327.48,727.94 ccw(c277.79,774.18) 345.67,774.18 v1(345.67,935.63)
USART1_TX: U2.45 U12.1 | length 622.9
  Top Layer 1 w10: U2.45@102.36,712.59 v1(102.36,750) ; v1(386.42,934.84) ccw(c386.42,965.28) 416.86,965.28 U12.1@416.85,995.87
  Bottom Layer 1 w10: v1(102.36,750) 134.35,718.01 ccw(c205,788.78) 205,688.78 293.39,688.78 ccw(c293.39,762.71) 345.67,710.43 357.13,721.89 ccw(c286.42,792.6) 386.42,792.6 v1(386.42,934.84)
VBUS: C29.2 Q9.K R49.2 U2.13 | length 2826.8
  Top Layer 1 w10: U2.13@-74.8,1066.52 -74.29,1074.1 -73.78,1074.1 -72.7,1082.1 ccw(c-92.52,1084.8) -72.59,1083.06 cw(c-60.63,1082.08) -72.52,1083.68 ccw(c-92.36,1086.25) -72.36,1086.19 -72.36,1099.53 cw(c-52.36,1099.53) -67.53,1112.55 v1(-67.32,1112.8) ; C29.2@1015.82,-586.52 1018.24,-582.32 1031.95,-558.47 1032.31,-557.84 R49.2@1034.72,-553.64 1038.66,-550.32 1039.35,-549.13 v1(1063.7,-525.37)
  SIG w10: v1(-67.32,1112.8) cw(c-21.22,1066.7) -21.22,1131.89 124.74,1131.89 ccw(c124.74,1176.25) 156.1,1144.88 cw(c183.19,1117.79) 183.19,1156.1 419.01,1156.1 cw(c419.01,1056.1) 489.72,1126.81 910.99,705.55 ccw(c976.18,770.74) 976.18,678.54 cw(c976.18,623.42) 1015.16,662.4 1130.36,547.2 cw(c1059.65,476.49) 1159.65,476.49 1159.65,-388.01 cw(c1059.65,-388.01) 1130.36,-458.72 v1(1063.7,-525.37)
  Bottom Layer 1 w20: Q9.K@964.76,-438.81 1042.57,-516.62 ccw(c1063.7,-495.49) v1(1063.7,-525.37)
pads on no net: CN4.5 CN4.6 M1.0 M2.0 U2.3 U2.4 U2.5 U2.7 U2.17 U2.28 U2.33 U2.34 U2.51 U2.53 U2.54 U2.55 U2.56 U2.57 U2.58 U2.60 U4.4 U10.6
copper on no net:
  other v3: 467.04,-1127.58 -863.02,-863.02 862.99,-863.02 -863.02,862.99 862.99,862.99 -467.07,1127.56

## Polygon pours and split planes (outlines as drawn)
GND on Top Layer 1 "GND-GND 1" (solid, remove dead copper, pour order 54): -1185.04,640.35 -1185.04,1353.35 1413.58,1353.35 1413.58,-1394.49 376.38,-1394.49 376.38,-378.94 -378.09,-378.94 -378.09,640.35
CANL on Top Layer 1 "Top Layer 1-5V" (solid, pour order 48): 1071.26,242.91 989.37,242.91 989.37,282.3 1071.26,282.3
3V3 on Top Layer 1 "Top Layer 1-5V" (solid, pour order 47): 848.98,-397.21 926.22,-263.41 1008.02,-310.64 930.78,-444.44
48V on Top Layer 1 "Top Layer 1-48V" (solid, pour order 30): -1407.28,-1399.02 -1407.28,428.74 369.69,428.74 369.69,-1399.02
B on Top Layer 1 "Top Layer 1-B" (solid, pour order 26): -1133.66,-197.25 -1133.66,-27.36 -761.22,-27.36 -761.22,-223.62 -1107.29,-223.62 cw(c-1107.29,-197.25)
GND on Top Layer 1 "Top Layer 1-GND" (solid, pour order 29): -714.57,-483.27 -714.57,-270.08 -756.5,-270.08 -756.5,201.18 -691.73,201.18 -691.73,630.51 -383.27,630.51 -383.27,23.43 369.49,23.43 369.49,-831.89 -389.17,-831.89 cw(c-389.17,-711.18) -474.53,-796.53 -579.61,-691.46 cw(c-494.25,-606.1) -614.96,-606.1 -614.96,-483.27
C on Top Layer 1 "Top Layer 1-C" (solid, pour order 28): -1007.68,-584.03 -1007.68,-508.86 -618.11,-508.86 -618.11,-634.03 -957.68,-634.03 cw(c-957.68,-584.03)
NetQ6_S on Top Layer 1 "Top Layer 1-NetQ6_S" (solid, pour order 27): -893.9,-430.91 cw(c-893.9,-423.23) -901.57,-423.23 -901.57,-230.71 -819.68,-230.71 -819.68,-335.24 -718.5,-335.24 -718.5,-496.26 -885.04,-496.26 -885.04,-439.76 ccw(c-893.9,-439.76)
NetQ4_S on Top Layer 1 "Top Layer 1-NetQ4_S" (solid, pour order 25): -1006.5,-17.72 -1006.5,200.98 -875.2,200.98 -875.2,105.91 ccw(c-861.02,105.91) -861.02,91.73 -761.61,91.73 -761.61,-17.72
A on Top Layer 1 "Top Layer 1-A" (solid, pour order 24): -1056.9,206.89 cw(c-1056.9,233.26) -1083.27,233.26 -1083.27,393.9 -700,393.9 -700,206.89
NetQ2_S on Top Layer 1 "Top Layer 1-NetQ2_S" (solid, pour order 23): -958.07,403.35 -700.39,403.35 -700.39,515.16 -805.91,515.16 cw(c-805.91,536.02) -826.77,536.02 -826.77,626.97 -958.07,626.97
3V3 on POWER "POWER-3V3" (solid, pour order 51): -1849.02,-1611.02 -1849.02,1741.93 1655.12,1741.93 1655.12,-1611.02
48V on POWER "Top Layer 1-48V" (solid, pour order 37): -382.86,786.02 -382.86,23.23 369.69,23.23 369.69,-1399.02 -1407.28,-1399.02 -1407.28,786.02
A3V3 on POWER "Top Layer 1-5V" (solid, pour order 50): -85.24,874.41 -426.57,874.41 -426.57,1325.98 -85.24,1325.98
NetQ6_S on POWER "Top Layer 1-NetQ6_S" (solid, pour order 36): -893.9,-430.91 cw(c-893.9,-423.23) -901.57,-423.23 -901.57,-230.71 -819.68,-230.71 -819.68,-335.24 -718.5,-335.24 -718.5,-496.26 -885.04,-496.26 -885.04,-439.76 ccw(c-893.9,-439.76)
B on POWER "Top Layer 1-B" (solid, pour order 35): -1133.66,-197.25 -1133.66,-27.36 -761.22,-27.36 -761.22,-223.62 -1107.29,-223.62 cw(c-1107.29,-197.25)
NetQ4_S on POWER "Top Layer 1-NetQ4_S" (solid, pour order 34): -1006.5,-17.72 -1006.5,200.98 -875.2,200.98 -875.2,105.91 ccw(c-861.02,105.91) -861.02,91.73 -761.61,91.73 -761.61,-17.72
A on POWER "Top Layer 1-A" (solid, pour order 33): -1056.9,206.89 cw(c-1056.9,233.26) -1083.27,233.26 -1083.27,393.9 -700,393.9 -700,206.89
NetQ2_S on POWER "Top Layer 1-NetQ2_S" (solid, pour order 32): -958.07,403.35 -700.39,403.35 -700.39,515.16 -805.91,515.16 cw(c-805.91,536.02) -826.77,536.02 -826.77,626.97 -958.07,626.97
C on POWER "Top Layer 1-C" (solid, pour order 31): -1007.68,-584.03 -1007.68,-508.86 -618.11,-508.86 -618.11,-634.03 -957.68,-634.03 cw(c-957.68,-584.03)
GND on Bottom Layer 1 "GND-GND 1" (solid, remove dead copper, pour order 55): -1185.04,640.35 -1185.04,1353.35 1413.58,1353.35 1413.58,-1394.49 376.38,-1394.49 376.38,-378.94 -378.09,-378.94 -378.09,640.35
GND on Bottom Layer 1 "Top Layer 1-GND" (solid, remove dead copper, pour order 44): -1500,201.18 -1500,630.51 -383.27,630.51 -383.27,23.43 369.49,23.43 369.49,-1347.44 -1500,-1347.44
A3V3 on Bottom Layer 1 "Top Layer 1-5V" (solid, pour order 49): -176.77,876.49 -176.77,989.96 -31.3,989.96 -31.3,876.49
5V on Bottom Layer 1 "Top Layer 1-5V" (solid, pour order 21): 550.49,-752.03 672.56,-822.51 636.43,-885.1 514.35,-814.62
A on Bottom Layer 1 "Top Layer 1-A" (solid, pour order 39): -1056.9,206.89 cw(c-1056.9,233.26) -1083.27,233.26 -1083.27,393.9 -700,393.9 -700,206.89
NetQ6_S on Bottom Layer 1 "Top Layer 1-NetQ6_S" (solid, pour order 42): -893.9,-430.91 cw(c-893.9,-423.23) -901.57,-423.23 -901.57,-230.71 -819.68,-230.71 -819.68,-335.24 -718.5,-335.24 -718.5,-496.26 -885.04,-496.26 -885.04,-439.76 ccw(c-893.9,-439.76)
C on Bottom Layer 1 "Top Layer 1-C" (solid, pour order 43): -1007.68,-584.03 -1007.68,-508.86 -618.11,-508.86 -618.11,-634.03 -957.68,-634.03 cw(c-957.68,-584.03)
B on Bottom Layer 1 "Top Layer 1-B" (solid, pour order 41): -1133.66,-197.25 -1133.66,-27.36 -761.22,-27.36 -761.22,-223.62 -1107.29,-223.62 cw(c-1107.29,-197.25)
NetQ4_S on Bottom Layer 1 "Top Layer 1-NetQ4_S" (solid, pour order 40): -1006.5,-17.72 -1006.5,200.98 -875.2,200.98 -875.2,105.91 ccw(c-861.02,105.91) -861.02,91.73 -761.61,91.73 -761.61,-17.72
NetQ2_S on Bottom Layer 1 "Top Layer 1-NetQ2_S" (solid, pour order 38): -958.07,403.35 -700.39,403.35 -700.39,515.16 -805.91,515.16 cw(c-805.91,536.02) -826.77,536.02 -826.77,626.97 -958.07,626.97
GND on GND (Mid4) "GND-GND" (solid, pour order 53): -1185.04,640.35 -1185.04,1353.35 1413.58,1353.35 1413.58,-1394.49 376.38,-1394.49 376.38,-378.94 -378.09,-378.94 -378.09,640.35
GND on GND (Mid4) "Top Layer 1-GND" (solid, remove dead copper, pour order 46): -1500,201.18 -1500,630.51 -383.27,630.51 -383.27,23.43 369.49,23.43 369.49,-1347.44 -1500,-1347.44
GND on GND "GND-GND 1" (solid, pour order 52): -1185.04,640.35 -1185.04,1353.35 1413.58,1353.35 1413.58,-1394.49 376.38,-1394.49 376.38,-378.94 -378.09,-378.94 -378.09,640.35
GND on GND "Top Layer 1-GND" (solid, remove dead copper, pour order 45): -1500,201.18 -1500,630.51 -383.27,630.51 -383.27,23.43 369.49,23.43 369.49,-1347.44 -1500,-1347.44

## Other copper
Top Layer 1:
  pour cut-out: -545.81,1127.56 ccw(c-467.07,1127.56) -467.07,1048.82 ccw(c-467.07,1127.56) -388.33,1127.56 ccw(c-467.07,1127.56) -467.07,1206.3 ccw(c-467.07,1127.56)
  pour cut-out: 388.3,-1127.58 ccw(c467.04,-1127.58) 467.04,-1206.32 ccw(c467.04,-1127.58) 545.78,-1127.58 ccw(c467.04,-1127.58) 467.04,-1048.84 ccw(c467.04,-1127.58)
  pour cut-out: 747.89,1068.17 cw(c-292.32,-292.32) 1068.17,747.89 ccw(c1005.62,700.07) 953.76,759.31 cw(c862.99,862.99) 759.31,953.76 ccw(c700.07,1005.62)
  pour cut-out: 1068.17,-747.92 cw(c-292.32,292.29) 747.89,-1068.2 ccw(c700.07,-1005.65) 759.31,-953.78 cw(c862.99,-863.02) 953.76,-759.34 ccw(c1005.62,-700.09)
  pour cut-out: -440.55,902.05 cw(c-440.55,923.02) -461.52,923.02 cw(c-440.55,923.02) -440.55,943.99 cw(c-440.55,923.02) -419.58,923.02 cw(c-440.55,923.02)
  pour cut-out: -339.96,1061.1 cw(c-339.96,1082.08) -360.93,1082.08 cw(c-339.96,1082.08) -339.96,1103.05 cw(c-339.96,1082.08) -318.99,1082.08 cw(c-339.96,1082.08)
  pour cut-out: -252.17,1159.24 cw(c-252.17,1180.21) -273.14,1180.21 cw(c-252.17,1180.21) -252.17,1201.18 cw(c-252.17,1180.21) -231.2,1180.21 cw(c-252.17,1180.21)
  pour cut-out: -1068.2,747.89 cw(c292.29,-292.32) -747.92,1068.17 ccw(c-700.09,1005.62) -759.34,953.76 cw(c-863.02,862.99) -953.78,759.31 ccw(c-1005.65,700.07)
  pour cut-out: -747.92,-1068.2 cw(c292.29,292.29) -1068.2,-747.92 ccw(c-1005.65,-700.09) -953.78,-759.34 cw(c-863.02,-863.02) -759.34,-953.78 ccw(c-700.09,-1005.65)
GND:
  pour cut-out: -252.17,1159.24 cw(c-252.17,1180.21) -273.14,1180.21 cw(c-252.17,1180.21) -252.17,1201.18 cw(c-252.17,1180.21) -231.2,1180.21 cw(c-252.17,1180.21)
  pour cut-out: -440.55,902.05 cw(c-440.55,923.02) -461.52,923.02 cw(c-440.55,923.02) -440.55,943.99 cw(c-440.55,923.02) -419.58,923.02 cw(c-440.55,923.02)
  pour cut-out: -339.96,1061.1 cw(c-339.96,1082.08) -360.93,1082.08 cw(c-339.96,1082.08) -339.96,1103.05 cw(c-339.96,1082.08) -318.99,1082.08 cw(c-339.96,1082.08)
  pour cut-out: -739.47,-333.04 cw(c-739.47,-312.07) -760.44,-312.07 cw(c-739.47,-312.07) -739.47,-291.1 cw(c-739.47,-312.07) -718.5,-312.07 cw(c-739.47,-312.07)
  pour cut-out: -809.25,95.76 cw(c-809.25,116.73) -830.22,116.73 cw(c-809.25,116.73) -809.25,137.7 cw(c-809.25,116.73) -788.28,116.73 cw(c-809.25,116.73)
GND (Mid4):
  pour cut-out: -440.55,902.05 cw(c-440.55,923.02) -461.52,923.02 cw(c-440.55,923.02) -440.55,943.99 cw(c-440.55,923.02) -419.58,923.02 cw(c-440.55,923.02)
  pour cut-out: -339.96,1061.1 cw(c-339.96,1082.08) -360.93,1082.08 cw(c-339.96,1082.08) -339.96,1103.05 cw(c-339.96,1082.08) -318.99,1082.08 cw(c-339.96,1082.08)
  pour cut-out: -252.17,1159.24 cw(c-252.17,1180.21) -273.14,1180.21 cw(c-252.17,1180.21) -252.17,1201.18 cw(c-252.17,1180.21) -231.2,1180.21 cw(c-252.17,1180.21)
  pour cut-out: -739.47,-333.04 cw(c-739.47,-312.07) -760.44,-312.07 cw(c-739.47,-312.07) -739.47,-291.1 cw(c-739.47,-312.07) -718.5,-312.07 cw(c-739.47,-312.07)
  pour cut-out: -809.25,95.76 cw(c-809.25,116.73) -830.22,116.73 cw(c-809.25,116.73) -809.25,137.7 cw(c-809.25,116.73) -788.28,116.73 cw(c-809.25,116.73)
Bottom Layer 1:
  pour cut-out: -809.25,95.76 cw(c-809.25,116.73) -830.22,116.73 cw(c-809.25,116.73) -809.25,137.7 cw(c-809.25,116.73) -788.28,116.73 cw(c-809.25,116.73)
  pour cut-out: -739.38,-333.14 cw(c-739.38,-312.17) -760.35,-312.17 cw(c-739.38,-312.17) -739.38,-291.19 cw(c-739.38,-312.17) -718.41,-312.17 cw(c-739.38,-312.17)

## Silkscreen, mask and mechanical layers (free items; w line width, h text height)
Top Overlay:
  circle w11.81: c467.04,-1127.58 r78.74
  circle w11.81: c-467.07,1127.56 r78.74
  circle w11.81: c467.04,-1127.58 r78.74
  circle w11.81: c-467.07,1127.56 r78.74
  lines w11.81: -1066.59,-741.89 cw(c-0.01,-0.01) -741.89,1066.56 ; -1066.59,-741.89 ccw(c-0.01,-0.01) 741.86,-1066.59 ; -1066.59,-741.89 ccw(c-1001.95,-696.93) -951.43,-757.32 ; -1066.59,-741.89 ccw(c-0.01,-0.01) 741.86,-1066.59 ; -1066.59,-741.89 ccw(c-1001.95,-696.93) -951.43,-757.32 ; -1066.59,-741.89 cw(c-0.01,-0.01) -741.89,1066.56 ; -951.43,-757.32 cw(c-863.02,-863.02) -760.24,-954.8 ccw(c-863.02,-863.02) -951.43,-757.32 ; -951.43,757.3 ccw(c-1001.95,696.9) -1066.59,741.86 cw(c-1001.95,696.9) -951.43,757.3 ; -951.43,757.3 ccw(c-863.02,862.99) -757.32,951.4 ; -951.43,757.3 ccw(c-863.02,862.99) -757.32,951.4 ; -757.32,951.4 cw(c-696.93,1001.92) -741.89,1066.56 ; -757.32,951.4 cw(c-696.93,1001.92) -741.89,1066.56 ; -741.89,1066.56 cw(c-0.01,-0.01) 1066.56,741.86 ; -741.89,1066.56 cw(c-0.01,-0.01) 1066.56,741.86 ; 741.86,-1066.59 ccw(c-0.01,-0.01) 1066.56,741.86 ; 741.86,-1066.59 ccw(c696.9,-1001.95) 757.3,-951.43 ; 741.86,-1066.59 ccw(c696.9,-1001.95) 757.3,-951.43 ; 741.86,-1066.59 ccw(c-0.01,-0.01) 1066.56,741.86 ; 757.3,-951.43 cw(c862.99,-863.02) 951.4,-757.32 ; 757.3,-951.43 cw(c862.99,-863.02) 951.4,-757.32 ; 951.4,-757.32 ccw(c1001.92,-696.93) 1066.56,-741.89 cw(c1001.92,-696.93) 951.4,-757.32 ; 951.4,757.3 cw(c862.99,862.99) 760.21,954.77 ccw(c862.99,862.99) 951.4,757.3 ; 951.4,757.3 cw(c1001.92,696.9) 1066.56,741.86 ; 951.4,757.3 cw(c1001.92,696.9) 1066.56,741.86 ; -757.32,-951.43 ccw(c-696.93,-1001.95) -741.89,-1066.59 cw(c-696.93,-1001.95) -757.32,-951.43 ; 741.86,1066.56 cw(c696.9,1001.92) 757.3,951.4 ccw(c696.9,1001.92) 741.86,1066.56
  text "DBG / GRT" at 529.53,988.58 h40
  text "DBG / GRT" at 529.53,988.58 h40
  text "SWD / GDC" at 354.33,608.27 h40
  text "NTC" at 517.13,331.5 h40
  text "ENC" at 680.32,275.2 h40 r300
  text "CAN / LHG" at 820.28,-163.19 h40
Bottom Overlay:
  circle w11.81: c-0.01,-0.01 r1122.05
Mechanical 13:
  circle w5.91: c-0.01,-0.01 r2.95
  circle w5.91: c-0.01,-0.01 r2.95
  circle w2: c-863.02,862.99 r43.31
  circle w2: c-467.07,1127.56 r43.31
  circle w2: c467.04,-1127.58 r43.31
  circle w2: c-863.02,-863.02 r43.31
  circle w2: c862.99,-863.02 r43.31
  circle w2: c862.99,862.99 r43.31
  circle w1.97: c0,0 r610.24
  lines w2: -1066.59,-741.89 cw(c-0.01,-0.01) -741.89,1066.56 cw(c-0.01,-0.01) 1066.56,741.86 cw(c-0.01,-0.01) 741.86,-1066.59 cw(c-0.01,-0.01) -1066.59,-741.89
